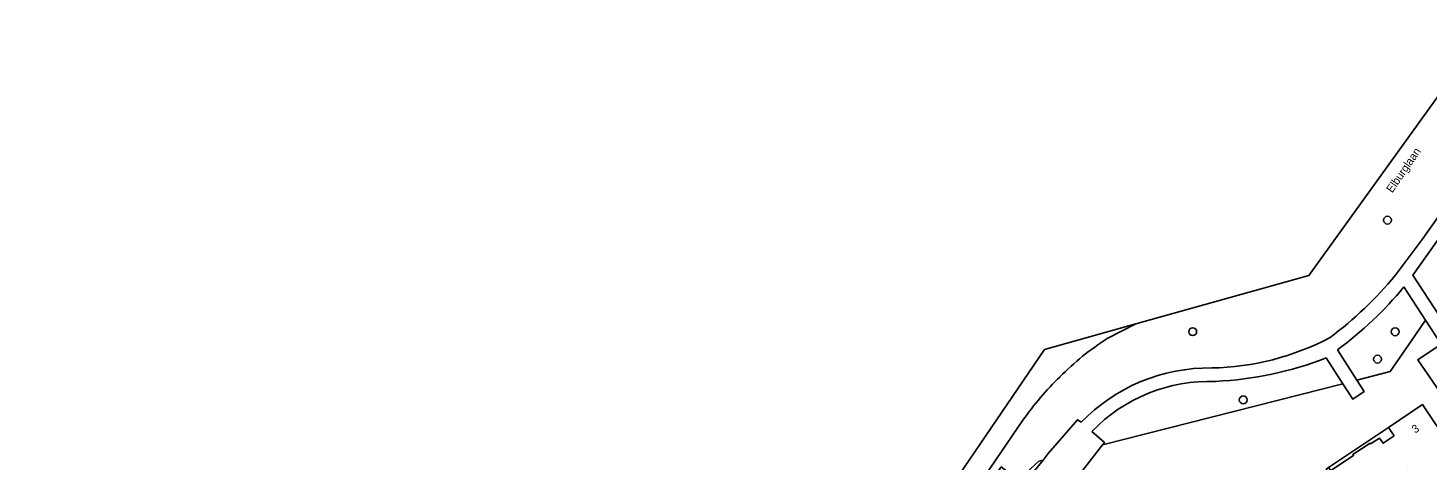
# Model space of a CAD drawing. Extents: x 158793 to 159888, y 384317 to 385256.
# Drawn here: x 158887.2 to 159062, y 384928.9 to 384982.9 of the extents above; entities that cross this region are included whole.
import ezdxf

# ---------------------------------------------------------------- set-up
doc = ezdxf.new("R2010")
doc.units = 0
for name, color, linetype in [('IMGEO_Berm_groen', 7, 'Continuous'), ('IMGEO_Boom', 7, 'Continuous'), ('IMGEO_Erf', 7, 'Continuous'), ('IMGEO_Groenvoorziening', 7, 'Continuous'), ('IMGEO_Openbare_ruimte_label', 7, 'Continuous'), ('IMGEO_Pand', 7, 'Continuous'), ('IMGEO_Pand_nummerreeks', 7, 'Continuous'), ('IMGEO_Pand_overbouw', 7, 'Continuous'), ('IMGEO_Rijbaan_lokaal_gesloten', 7, 'Continuous'), ('IMGEO_Rijbaan_lokaal_open', 7, 'Continuous'), ('IMGEO_Voetpad_gesloten', 7, 'Continuous')]:
    doc.layers.add(name, color=color, linetype=linetype)

msp = doc.modelspace()

# ---------------------------------------------------------------- linework, layer by layer
at = {"layer": 'IMGEO_Berm_groen'}
for points in [[(159058, 384951.94), (159061.37, 384956.43), (159077.33, 384978.98), (159073.53, 384981.68), (159072.78, 384980.6), (159069.49, 384982.85), (159065.05, 384976.68), (159070.18, 384973.08), (159069.87, 384972.64), (159064.74, 384976.24), (159047.24, 384951.92), (159025.62, 384945.88)], [(159025.62, 384945.88), (159022.05, 384944.07)], [(159011.51, 384933.86), (159006.1, 384925.91), (159003.26, 384921.81), (159003.57, 384921.58), (159003.85, 384920.8), (159008.8, 384928.03), (159010.93, 384926.39), (159013.51, 384928.75), (159014.02, 384928.88), (159014.68, 384929.69), (159018.32, 384933.91), (159018.8, 384933.6)]]:
    msp.add_lwpolyline(points, dxfattribs=at)
for centre, radius, start, end in [((159020.96, 384982.61), 48.09, 306.9664, 320.3782), ((159041.17, 384914.3), 35.38, 122.7235, 135.0394), ((159034.47, 384973.47), 33.09, 271.0944, 297.7469), ((159034.79, 384918.15), 22.24, 89.2094, 136.0044), ((159043.16, 384911.59), 38.7, 134.2768, 144.872)]:
    msp.add_arc(centre, radius, start, end, dxfattribs=at)
at = {"layer": 'IMGEO_Boom'}
for centre in [(159057.05, 384958.85), (159032.72, 384944.92), (159058.01, 384944.91), (159055.8, 384941.49), (159039.03, 384936.4)]:
    msp.add_circle(centre, 0.489, dxfattribs=at)
at = {"layer": 'IMGEO_Erf'}
msp.add_lwpolyline([(159070.12, 384927.64), (159063.2, 384937.96), (159060.82, 384941.42), (159063.77, 384943.36), (159061.81, 384946.35), (159060.1, 384943.86), (159057.39, 384939.93), (159053.23, 384938.87), (159054.12, 384937.46), (159052.74, 384936.48), (159051.48, 384938.42), (159021.44, 384930.77), (159014.24, 384921.49)], dxfattribs=at)
msp.add_lwpolyline([(159049.4, 384927.74), (159049.7, 384927.95), (159049.97, 384927.58), (159052.81, 384929.47), (159052.74, 384929.58), (159054.87, 384931), (159054.94, 384930.9), (159056.04, 384931.63), (159056.49, 384930.98), (159057.87, 384931.93), (159057.16, 384932.96), (159061.43, 384935.82), (159068.1, 384925.87), (159065.51, 384924.12), (159063.07, 384922.48), (159062.93, 384922.68), (159065.36, 384924.33), (159063.84, 384926.59), (159061.38, 384924.93), (159059.6, 384927.58), (159052.67, 384922.92)], close=True, dxfattribs=at)
at = {"layer": 'IMGEO_Groenvoorziening'}
for points in [[(159089.83, 384969.81), (159078.68, 384977.98), (159060.22, 384951.96), (159062.89, 384947.9)], [(159061.81, 384946.35), (159059.08, 384950.51)], [(159050.81, 384942.67), (159053.23, 384938.87), (159057.39, 384939.93), (159060.1, 384943.86), (159061.81, 384946.35)], [(159051.48, 384938.42), (159049.39, 384941.65)], [(159020.13, 384932.46), (159021.69, 384931.08), (159021.44, 384930.77), (159051.48, 384938.42)]]:
    msp.add_lwpolyline(points, dxfattribs=at)
for centre, radius, start, end in [((159023.84, 384979.41), 45.58, 306.2837, 320.6434), ((159033.66, 384981.72), 43.05, 272.552, 291.4215), ((159034.85, 384918.3), 20.42, 87.9585, 136.1231)]:
    msp.add_arc(centre, radius, start, end, dxfattribs=at)
at = {"layer": 'IMGEO_Pand'}
msp.add_lwpolyline([(159057.16, 384932.96), (159057.87, 384931.93), (159056.49, 384930.98), (159056.04, 384931.63), (159054.94, 384930.9), (159054.87, 384931), (159052.74, 384929.58), (159052.81, 384929.47), (159049.97, 384927.58), (159049.7, 384927.95), (159049.4, 384927.74), (159052.67, 384922.92), (159059.6, 384927.58), (159061.38, 384924.93), (159063.84, 384926.59), (159065.36, 384924.33), (159065.51, 384924.12), (159068.1, 384925.87), (159061.43, 384935.82)], close=True, dxfattribs=at)
at = {"layer": 'IMGEO_Pand_overbouw'}
msp.add_lwpolyline([(159049.7, 384927.95), (159049.97, 384927.58), (159052.81, 384929.47), (159052.74, 384929.58), (159054.87, 384931), (159054.94, 384930.9), (159056.04, 384931.63), (159056.49, 384930.98), (159057.87, 384931.93), (159057.16, 384932.96)], close=True, dxfattribs=at)
at = {"layer": 'IMGEO_Rijbaan_lokaal_gesloten'}
for points in [[(159022.05, 384944.07), (159025.62, 384945.88), (159014.22, 384942.69), (158887.22, 384756.16)], [(159006.1, 384925.91), (159011.51, 384933.86)]]:
    msp.add_lwpolyline(points, dxfattribs=at)
for centre, radius, start, end in [((159041.17, 384914.3), 35.38, 122.7235, 135.0394), ((159043.16, 384911.59), 38.7, 134.2768, 144.872)]:
    msp.add_arc(centre, radius, start, end, dxfattribs=at)
at = {"layer": 'IMGEO_Rijbaan_lokaal_open'}
msp.add_lwpolyline([(159148.2, 384834.8), (159118.86, 384878.46), (159111.77, 384888.57), (159104.97, 384899.16), (159103.81, 384898.41), (159096.87, 384908.49), (159087.73, 384922.13), (159083.94, 384919.6), (159075.86, 384931.64), (159073.19, 384929.85), (159064.37, 384942.98), (159064.01, 384943.52), (159063.77, 384943.36), (159060.82, 384941.42), (159063.2, 384937.96), (159070.12, 384927.64), (159074.59, 384920.97)], dxfattribs=at)
at = {"layer": 'IMGEO_Voetpad_gesloten'}
for points in [[(159059.08, 384950.51), (159061.81, 384946.35), (159063.77, 384943.36), (159064.01, 384943.52), (159064.37, 384942.98), (159065.56, 384943.77), (159065.18, 384944.41), (159062.89, 384947.9), (159060.22, 384951.96), (159078.68, 384977.98), (159077.33, 384978.98), (159061.37, 384956.43), (159058, 384951.94)], [(159049.39, 384941.65), (159051.48, 384938.42), (159052.74, 384936.48), (159054.12, 384937.46), (159053.23, 384938.87), (159050.81, 384942.67)], [(159018.8, 384933.6), (159018.32, 384933.91), (159014.68, 384929.69), (159014.02, 384928.88), (159010.51, 384924.56), (159012, 384923.55), (159008.29, 384918.2), (159007.94, 384917.67), (159009.38, 384916.7), (159009.62, 384917.07), (159013.2, 384922.27), (159014.24, 384921.49), (159021.44, 384930.77), (159021.69, 384931.08), (159020.13, 384932.46)]]:
    msp.add_lwpolyline(points, dxfattribs=at)
for centre, radius, start, end in [((159020.96, 384982.61), 48.09, 306.9664, 320.3782), ((159023.84, 384979.41), 45.58, 306.2837, 320.6434), ((159034.47, 384973.47), 33.09, 271.0944, 297.7469), ((159033.66, 384981.72), 43.05, 272.552, 291.4215), ((159034.79, 384918.15), 22.24, 89.2094, 136.0044), ((159034.85, 384918.3), 20.42, 87.9585, 136.1231)]:
    msp.add_arc(centre, radius, start, end, dxfattribs=at)

# ---------------------------------------------------------------- texts
at = {"layer": 'IMGEO_Openbare_ruimte_label'}
msp.add_text('Elburglaan', height=1, rotation=55.5151, dxfattribs=at).set_placement((159057.64, 384962.19))
at = {"layer": 'IMGEO_Pand_nummerreeks'}
msp.add_text('3', height=1, rotation=33.8675, dxfattribs=at).set_placement((159060.5, 384932.18))

doc.saveas('drawing.dxf')
